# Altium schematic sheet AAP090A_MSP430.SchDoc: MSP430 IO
size 538 x 342 mm; Date: Not shown in title block; ApprovedBy: Not shown in title block; CheckedBy: Not shown in title block; Author: Not shown in title block; CompanyName: Not shown in title block; DrawnBy: LDN; Engineer: Not shown in title block; Organization: Not shown in title block; Address1: Not shown in title block; Address2: Not shown in title block; Address3: Not shown in title block; Address4: Not shown in title block; DocumentNumber: 2; Revision: Use project parameter SCH_Rev; SheetNumber: 2; SheetTotal: 6; PageSetup: Record=PageOptions¦CenterHorizontal=True¦CenterVertical=True¦PrintScale=1.00¦XCorrection=1.00¦YCorrection=1.00¦PrintKind=0¦BorderSize=5000000¦LeftOffset=0¦BottomOffset=0¦Orientation=2¦PaperLength=1000¦PaperWidth=1000¦Scale=100¦PaperSource=15¦PrintQuality=600¦MediaType=1¦DitherType=10¦PaperKind=Letter¦PrintScaleMode=1
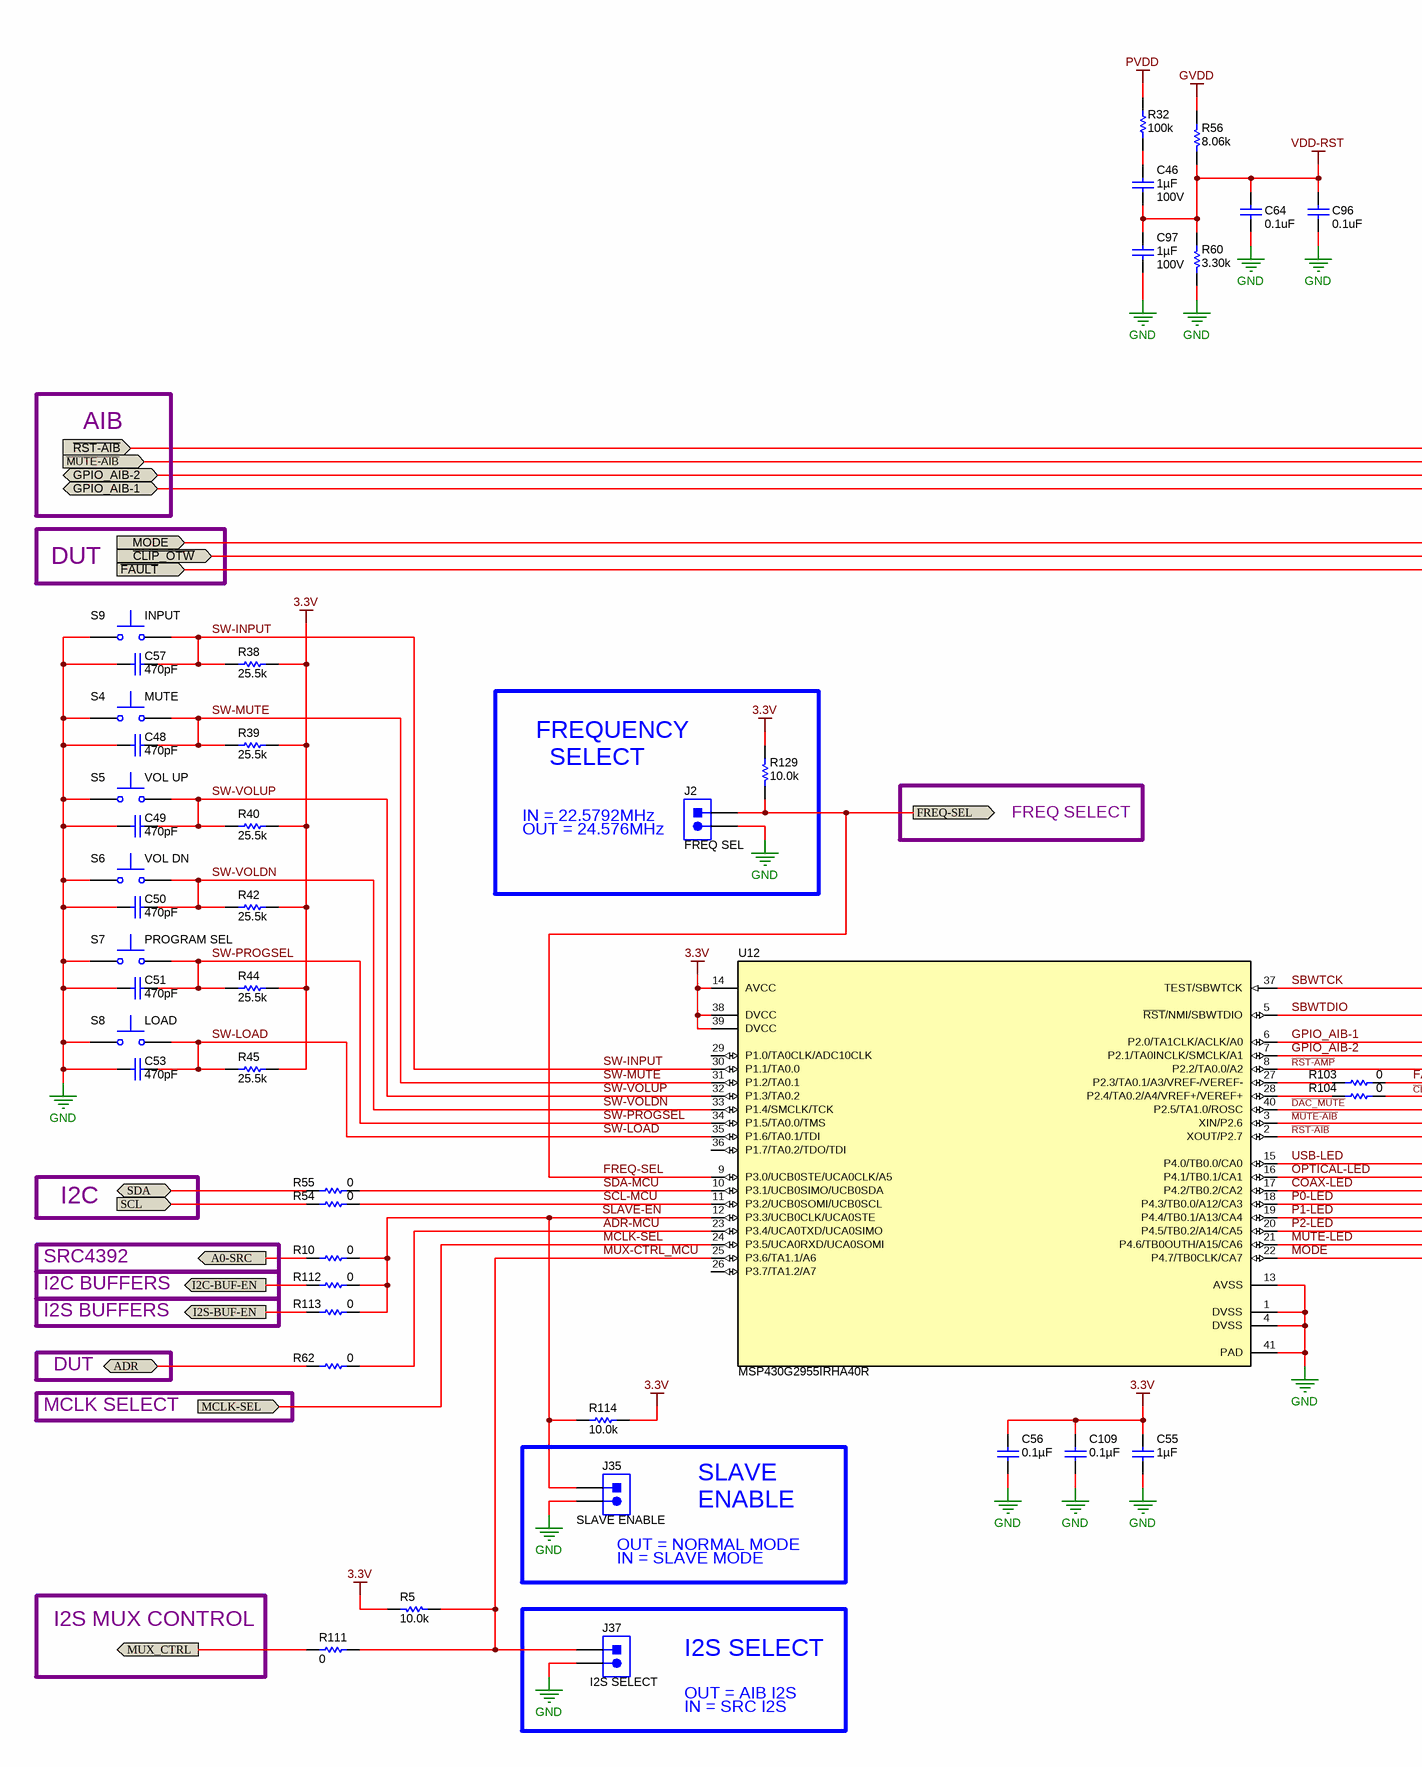
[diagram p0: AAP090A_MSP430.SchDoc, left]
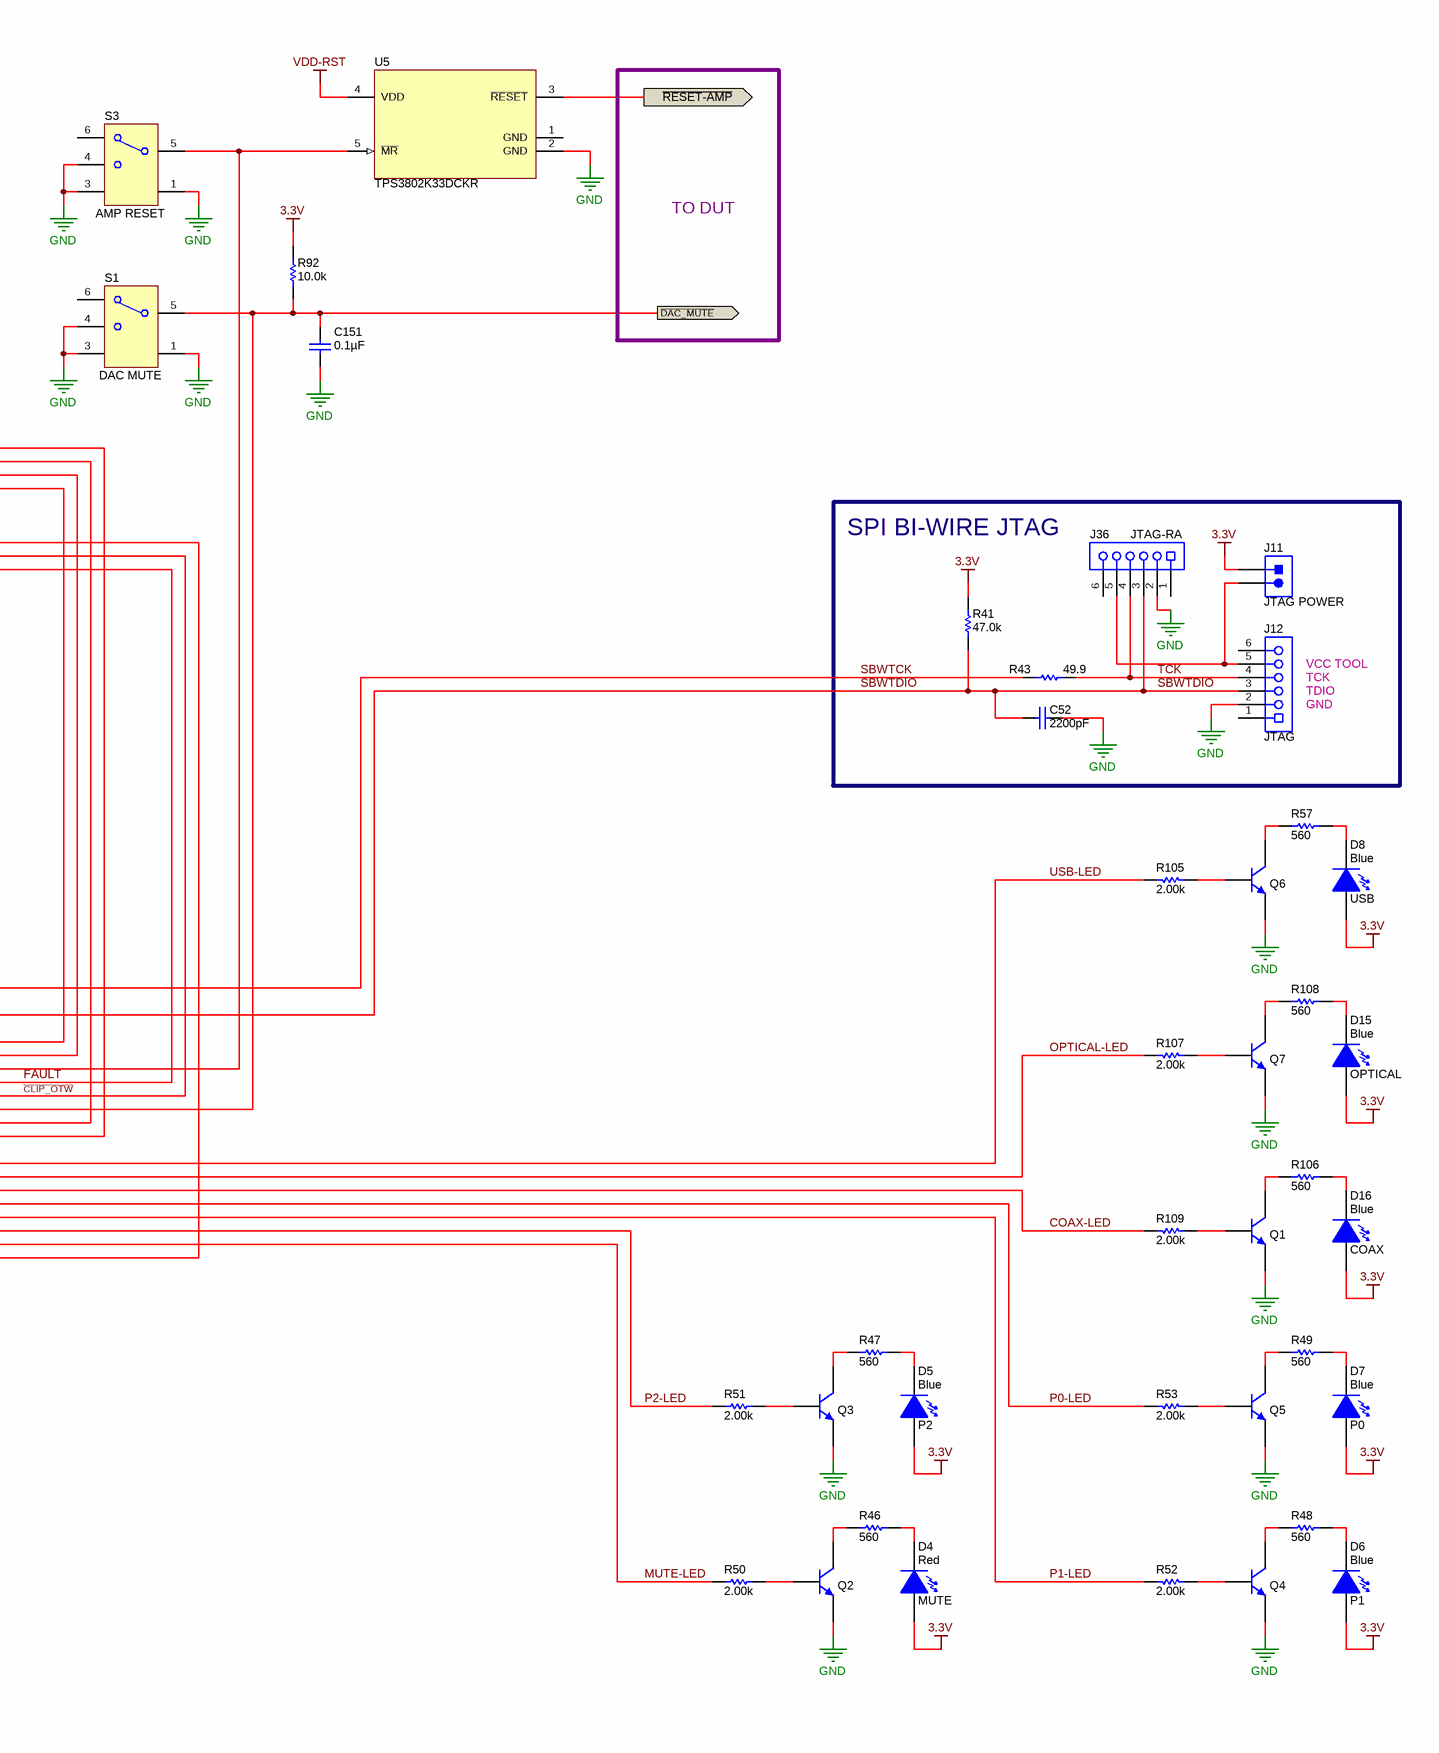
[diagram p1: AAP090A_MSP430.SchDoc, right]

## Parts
C46  ValueDisplayed: 1µF  Value2: 100V  [1206_180L]  (hidden comment: GRM31CR72A105KA01L)
C48  ValueDisplayed: 470pF  [0402L]  (hidden comment: GRM1555C1E471JA01D)
C49  ValueDisplayed: 470pF  [0402L]  (hidden comment: GRM1555C1E471JA01D)
C50  ValueDisplayed: 470pF  [0402L]  (hidden comment: GRM1555C1E471JA01D)
C51  ValueDisplayed: 470pF  [0402L]  (hidden comment: GRM1555C1E471JA01D)
C52  ValueDisplayed: 2200pF  [0603L]  (hidden comment: 885012206036)
C53  ValueDisplayed: 470pF  [0402L]  (hidden comment: GRM1555C1E471JA01D)
C55  ValueDisplayed: 1µF  [0402L]  (hidden comment: GRM152R60J105ME15D)
C56  ValueDisplayed: 0.1µF  [0402L]  (hidden comment: GRM155R71A104KA01D)
C57  ValueDisplayed: 470pF  [0402L]  (hidden comment: GRM1555C1E471JA01D)
C64  value 0.1uF  [0603L]  (hidden comment: C0603C104K5RACTU)
C96  value 0.1uF  [0603L]  (hidden comment: C0603C104K5RACTU)
C97  ValueDisplayed: 1µF  Value2: 100V  [1206_180L]  (hidden comment: GRM31CR72A105KA01L)
C109  ValueDisplayed: 0.1µF  [0402L]  (hidden comment: GRM155R71A104KA01D)
C151  ValueDisplayed: 0.1µF  [0402L]  (hidden comment: GRM155R71A104KA01D)
D4  MUTE  value Red  [LED_LTST-C190_Red]
D5  P2  value Blue  [LB Q39G_BLUE]
D6  P1  value Blue  [LB Q39G_BLUE]
D7  P0  value Blue  [LB Q39G_BLUE]
D8  USB  value Blue  [LB Q39G_BLUE]
D15  OPTICAL  value Blue  [LB Q39G_BLUE]
D16  COAX  value Blue  [LB Q39G_BLUE]
J2  FREQ SEL  [Sullins_PBC02SAAN]
J11  JTAG POWER  [Sullins_PBC02SAAN]
J12  JTAG  [Mill-Max_851-XX-006-10-001000]
J35  SLAVE ENABLE  [Sullins_PBC02SAAN]
J36  JTAG-RA  [SULLINS_LPPB061NGCN-RC]
J37  I2S SELECT  [Sullins_PBC02SAAN]
Q1  MMBT2222A  [SOT-23]  (value not drawn)
Q2  MMBT2222A  [SOT-23]  (value not drawn)
Q3  MMBT2222A  [SOT-23]  (value not drawn)
Q4  MMBT2222A  [SOT-23]  (value not drawn)
Q5  MMBT2222A  [SOT-23]  (value not drawn)
Q6  MMBT2222A  [SOT-23]  (value not drawn)
Q7  MMBT2222A  [SOT-23]  (value not drawn)
R5  ValueDisplayed: 10.0k  [0201L]  (hidden comment: RC0201FR-0710KL)
R10  ValueDisplayed: 0  [0603L]  (hidden comment: DNP)
R32  ValueDisplayed: 100k  [0603L]  (hidden comment: RC0603FR-07100KL)
R38  ValueDisplayed: 25.5k  [0201L]  (hidden comment: RC0201FR-0725K5L)
R39  ValueDisplayed: 25.5k  [0201L]  (hidden comment: RC0201FR-0725K5L)
R40  ValueDisplayed: 25.5k  [0201L]  (hidden comment: RC0201FR-0725K5L)
R41  ValueDisplayed: 47.0k  [0402L]  (hidden comment: RC0402FR-0747KL)
R42  ValueDisplayed: 25.5k  [0201L]  (hidden comment: RC0201FR-0725K5L)
R43  ValueDisplayed: 49.9  [0402L]  (hidden comment: RC0402FR-0749R9L)
R44  ValueDisplayed: 25.5k  [0201L]  (hidden comment: RC0201FR-0725K5L)
R45  ValueDisplayed: 25.5k  [0201L]  (hidden comment: RC0201FR-0725K5L)
R46  ValueDisplayed: 560  [0603L]  (hidden comment: RC0603JR-07560RL)
R47  ValueDisplayed: 560  [0603L]  (hidden comment: RC0603JR-07560RL)
R48  ValueDisplayed: 560  [0603L]  (hidden comment: RC0603JR-07560RL)
R49  ValueDisplayed: 560  [0603L]  (hidden comment: RC0603JR-07560RL)
R50  ValueDisplayed: 2.00k  [0603L]  (hidden comment: RC0603FR-072KL)
R51  ValueDisplayed: 2.00k  [0603L]  (hidden comment: RC0603FR-072KL)
R52  ValueDisplayed: 2.00k  [0603L]  (hidden comment: RC0603FR-072KL)
R53  ValueDisplayed: 2.00k  [0603L]  (hidden comment: RC0603FR-072KL)
R54  ValueDisplayed: 0  [0603L]  (hidden comment: ERJ-3GEY0R00V)
R55  ValueDisplayed: 0  [0603L]  (hidden comment: ERJ-3GEY0R00V)
R56  ValueDisplayed: 8.06k  [0603L]  (hidden comment: RC0603FR-078K06L)
R57  ValueDisplayed: 560  [0603L]  (hidden comment: RC0603JR-07560RL)
R60  ValueDisplayed: 3.30k  [0603L]  (hidden comment: RC0603FR-073K3L)
R62  ValueDisplayed: 0  [0603L]  (hidden comment: ERJ-3GEY0R00V)
R92  ValueDisplayed: 10.0k  [0402L]  (hidden comment: ERJ-2RKF1002X)
R103  ValueDisplayed: 0  [0603L]  (hidden comment: ERJ-3GEY0R00V)
R104  ValueDisplayed: 0  [0603L]  (hidden comment: ERJ-3GEY0R00V)
R105  ValueDisplayed: 2.00k  [0603L]  (hidden comment: RC0603FR-072KL)
R106  ValueDisplayed: 560  [0603L]  (hidden comment: RC0603JR-07560RL)
R107  ValueDisplayed: 2.00k  [0603L]  (hidden comment: RC0603FR-072KL)
R108  ValueDisplayed: 560  [0603L]  (hidden comment: RC0603JR-07560RL)
R109  ValueDisplayed: 2.00k  [0603L]  (hidden comment: RC0603FR-072KL)
R111  ValueDisplayed: 0  [0402L]  (hidden comment: ERJ-2GE0R00X)
R112  ValueDisplayed: 0  [0603L]  (hidden comment: ERJ-3GEY0R00V)
R113  ValueDisplayed: 0  [0603L]  (hidden comment: ERJ-3GEY0R00V)
R114  ValueDisplayed: 10.0k  [0201L]  (hidden comment: RC0201FR-0710KL)
R129  ValueDisplayed: 10.0k  [0201L]  (hidden comment: RC0201FR-0710KL)
S1  DAC MUTE  [SW_200USP1T1A1M2]
S3  AMP RESET  [SW_200USP1T1A1M2]
S4  MUTE  [SW_TL1015AF160QG]
S5  VOL UP  [SW_TL1015AF160QG]
S6  VOL DN  [SW_TL1015AF160QG]
S7  PROGRAM SEL  [SW_TL1015AF160QG]
S8  LOAD  [SW_TL1015AF160QG]
S9  INPUT  [SW_TL1015AF160QG]
U5  TPS3802K33DCKR  [DCK0005A_N]
U12  MSP430G2955IRHA40R  [RHA0040B]

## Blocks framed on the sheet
SPI BI-WIRE JTAG: C52 J11 J12 J36 R41 R43
I2S SELECT: J37

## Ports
A0-SRC (out), ADR (bidir), FREQ-SEL (out), GPIO_AIB-1 (bidir), GPIO_AIB-2 (bidir), I2C-BUF-EN (out), I2S-BUF-EN (out), MCLK-SEL (in), MODE (in), MUX_CTRL (out), SCL (in), SDA (bidir), ~{CLIP_OTW} (in), ~{DAC_MUTE} (out), ~{FAULT} (in), ~{MUTE-AIB} (in), ~{RESET-AMP} (out), ~{RST-AIB} (in)

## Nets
3.3V: C55.2 C56.2 C109.2 D4.1(A) D5.1(A) D6.1(A) D7.1(A) D8.1(A) D15.1(A) D16.1(A) J11.1 R5.2 R38.1 R39.1 R40.1 R41.2 R42.1 R44.1 R45.1 R92.1 R114.2 R129.2 U12.14(AVCC) U12.38(DVCC) U12.39(DVCC)
GND: C48.2 C49.2 C50.2 C51.2 C52.1 C53.2 C55.1 C56.1 C57.2 C64.2 C96.2 C97.1 C109.1 C151.1 J2.2 J12.2 J35.2 J36.2 J37.2 Q1.2(E) Q2.2(E) Q3.2(E) Q4.2(E) Q5.2(E) Q6.2(E) Q7.2(E) R60.1 S1.1 S1.3 S1.4 S3.1 S3.3 S3.4 S4.1 S5.1 S6.1 S7.1 S8.1 S9.1 U5.2(GND) U12.1(DVSS) U12.4(DVSS) U12.13(AVSS) U12.41(PAD)
GVDD: R56.2
PVDD: R32.2
VDD-RST: C46.1 C64.1 C96.1 C97.2 R56.1 R60.2 U5.4(VDD)
~{CLIP_OTW}: R104.2 ; port ~{CLIP_OTW}
~{DAC_MUTE}: C151.2 R92.2 S1.5(COM) U12.40(P2.5/TA1.0/ROSC) ; port ~{DAC_MUTE}
~{FAULT}: R103.2 ; port ~{FAULT}
~{MUTE-AIB}: U12.3(XIN/P2.6) ; port ~{MUTE-AIB}
~{RESET-AMP}: U5.3(~{RESET}) ; port ~{RESET-AMP}
~{RST-AIB}: U12.2(XOUT/P2.7) ; port ~{RST-AIB}
~{RST-AMP}: S3.5(COM) U5.5(~{MR}) U12.8(P2.2/TA0.0/A2)
A0-SRC: R10.1 ; port A0-SRC
ADR: R62.1 ; port ADR
ADR-MCU: R62.2 U12.23(P3.4/UCA0TXD/UCA0SIMO)
COAX-LED: R109.2 U12.17(P4.2/TB0.2/CA2)
FREQ-SEL: J2.1 R129.1 U12.9(P3.0/UCB0STE/UCA0CLK/A5) ; port FREQ-SEL
GPIO_AIB-1: U12.6(P2.0/TA1CLK/ACLK/A0) ; port GPIO_AIB-1
GPIO_AIB-2: U12.7(P2.1/TA0INCLK/SMCLK/A1) ; port GPIO_AIB-2
I2C-BUF-EN: R112.1 ; port I2C-BUF-EN
I2S-BUF-EN: R113.1 ; port I2S-BUF-EN
MCLK-SEL: U12.24(P3.5/UCA0RXD/UCA0SOMI) ; port MCLK-SEL
MODE: U12.22(P4.7/TB0CLK/CA7) ; port MODE
MUTE-LED: R50.2 U12.21(P4.6/TB0OUTH/A15/CA6)
MUX-CTRL_MCU: J37.1 R5.1 R111.1 U12.25(P3.6/TA1.1/A6)
MUX_CTRL: R111.2 ; port MUX_CTRL
OPTICAL-LED: R107.2 U12.16(P4.1/TB0.1/CA1)
P0-LED: R53.2 U12.18(P4.3/TB0.0/A12/CA3)
P1-LED: R52.2 U12.19(P4.4/TB0.1/A13/CA4)
P2-LED: R51.2 U12.20(P4.5/TB0.2/A14/CA5)
SBWTCK: R43.1 U12.37(TEST/SBWTCK)
SBWTDIO: C52.2 J12.3 J36.3 R41.1 U12.5(~{RST}/NMI/SBWTDIO)
SCL: R54.1 ; port SCL
SCL-MCU: R54.2 U12.11(P3.2/UCB0SOMI/UCB0SCL)
SDA: R55.1 ; port SDA
SDA-MCU: R55.2 U12.10(P3.1/UCB0SIMO/UCB0SDA)
SLAVE-EN: J35.1 R10.2 R112.2 R113.2 R114.1 U12.12(P3.3/UCB0CLK/UCA0STE)
SW-INPUT: C57.1 R38.2 S9.2 U12.30(P1.1/TA0.0)
SW-LOAD: C53.1 R45.2 S8.2 U12.35(P1.6/TA0.1/TDI)
SW-MUTE: C48.1 R39.2 S4.2 U12.31(P1.2/TA0.1)
SW-PROGSEL: C51.1 R44.2 S7.2 U12.34(P1.5/TA0.0/TMS)
SW-VOLDN: C50.1 R42.2 S6.2 U12.33(P1.4/SMCLK/TCK)
SW-VOLUP: C49.1 R40.2 S5.2 U12.32(P1.3/TA0.2)
TCK: J12.4 J36.4 R43.2
USB-LED: R105.2 U12.15(P4.0/TB0.0/CA0)
NetC46_2: C46.2 R32.1
NetD4_2: D4.2(K) R46.1
NetD5_2: D5.2(K) R47.1
NetD6_2: D6.2(K) R48.1
NetD7_2: D7.2(K) R49.1
NetD8_2: D8.2(K) R57.1
NetD15_2: D15.2(K) R108.1
NetD16_2: D16.2(K) R106.1
NetJ11_2: J11.2 J12.5 J36.5
NetQ1_1: Q1.1(B) R109.1
NetQ1_3: Q1.3(C) R106.2
NetQ2_1: Q2.1(B) R50.1
NetQ2_3: Q2.3(C) R46.2
NetQ3_1: Q3.1(B) R51.1
NetQ3_3: Q3.3(C) R47.2
NetQ4_1: Q4.1(B) R52.1
NetQ4_3: Q4.3(C) R48.2
NetQ5_1: Q5.1(B) R53.1
NetQ5_3: Q5.3(C) R49.2
NetQ6_1: Q6.1(B) R105.1
NetQ6_3: Q6.3(C) R57.2
NetQ7_1: Q7.1(B) R107.1
NetQ7_3: Q7.3(C) R108.2
NetR103_1: R103.1 U12.27(P2.3/TA0.1/A3/VREF-/VEREF-)
NetR104_1: R104.1 U12.28(P2.4/TA0.2/A4/VREF+/VEREF+)

Not connected (* = marked no-connect by the designer): J12 1 6; J36 1 6; S1 6; S3 6; U5 1(GND); U12 26(P3.7/TA1.2/A7) 29(P1.0/TA0CLK/ADC10CLK) 36(P1.7/TA0.2/TDO/TDI)

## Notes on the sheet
- TO DUT
- AIB
- DUT
- (near J12) VCC TOOL
- (near J12) TDIO
- (near J12) TCK
- (near J12) GND
- FREQUENCY
- SELECT
- OUT = 24.576MHz
- IN = 22.5792MHz
- FREQ SELECT
- I2C
- I2C BUFFERS
- SRC4392
- I2S BUFFERS
- MCLK SELECT
- SLAVE
- ENABLE
- (near J35) OUT = NORMAL MODE
- (near J35) IN = SLAVE MODE
- I2S MUX CONTROL
- OUT = AIB I2S
- IN = SRC I2S

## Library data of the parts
C46 C97 = GRM31CR72A105KA01L: CAP, CERM, 1 µF, 100 V, +/- 10%, X7R, 1206; Manufacturer: MuRata; Polarized: N; CompType: Capacitor; Value: 1uF; U/M: EA; Cap_F: 0.000001; Tolerance_%: 10; Value1: Unknown; VDC_V: 100; TaMin_C: -55; TaMax_C: 125; Cap_Case: 2220; SizeArea_mm2: 5.12; SizeAreaWB_mm2: 10.92; SizeX_mm: 3.2; SizeY_mm: 1.6; SizeZ_mm: 1.8; AEC Category: Q200
C48-C51 C53 C57 = GRM1555C1E471JA01D: CAP, CERM, 470 pF, 25 V, +/- 5%, C0G/NP0, 0402; Manufacturer: MuRata; Polarized: N; CompType: Capacitor; Value: 470pF; U/M: EA; Cap_F: 0.00000000047; Tolerance_%: 5; Value1: Unknown; VDC_V: 25; Value2: 25V; TaMin_C: -55; TaMax_C: 125; Cap_Case: 0402; AEC Category: Q200; SizeArea_mm2: 0.5; SizeAreaWB_mm2: 3; SizeX_mm: 1; SizeZ_mm: 0.6
C52 = 885012206036: CAP, CERM, 2200 pF, 16 V, +/- 10%, X7R, 0603; Manufacturer: Wurth Elektronik; Polarized: N; CompType: Capacitor; Value: 2200pF; U/M: EA; Cap_F: 0.0000000022; Tolerance_%: 10; Value1: Unknown; VDC_V: 16; Value2: 16V; TaMin_C: -55; TaMax_C: 125; Cap_Case: 0603; AEC Category: Q200; SizeArea_mm2: 1.28; SizeAreaWB_mm2: 4.68; SizeX_mm: 1.6; SizeY_mm: 0.8; SizeZ_mm: 1
C55 = GRM152R60J105ME15D: CAP, CERM, 1 µF, 6.3 V,+/- 20%, X5R, 0402; Manufacturer: MuRata; Polarized: N; CompType: Capacitor; Value: 1uF; U/M: EA; Cap_F: 0.000001; Tolerance_%: 20; VDC_V: 6.3; Value2: 6.3V; TaMin_C: -55; TaMax_C: 85; Cap_Case: 0402; SizeArea_mm2: 0.5; SizeAreaWB_mm2: 3; SizeX_mm: 1; SizeZ_mm: 0.6; AEC Category: Q200; Green_Lifecycle: Active; Green_REACh: Passed
C56 C109 C151 = GRM155R71A104KA01D: CAP, CERM, 0.1 µF, 10 V, +/- 10%, X7R, 0402; Manufacturer: MuRata; Polarized: N; CompType: Capacitor; Value: 0.1uF; U/M: EA; Cap_F: 0.0000001; Tolerance_%: 10; Value1: Unknown; Value2: 10V; TaMin_C: -55; TaMax_C: 125; Cap_Case: 0402; AEC Category: Q200
C64 C96 = C0603C104K5RACTU: CAP, CERM, 0.1 µF, 50 V, +/- 10%, X7R, 0603; Manufacturer: Kemet; Polarized: N; CompType: Capacitor; ValueDisplayed: 0.1µF; U/M: EA; Cap_F: 0.0000001; Tolerance_%: 10; Value1: Unknown; VDC_V: 50; Value2: 50V; TaMin_C: -55; TaMax_C: 125; Cap_Case: 0603; AEC Category: Q200
D4 = LTST-C190CKT: LED, Red, SMD; Manufacturer: Lite-On; Vf_V: 2; Value2: 2V; Io_A: 0.02; Tjmax_C: 85; Power_TotalModule: 0.0625; Value1: 0.0625W; U/M: EA
D5-D8 D15 D16 = LB Q39G-L2N2-35-1: LED, Blue, SMD; Manufacturer: OSRAM; Vf_V: 2.85; Value2: 2.85V; Io_A: 0.15; Tjmax_C: 95; Value1: W; U/M: EA
J2 J11 J35 J37 = PBC02SAAN: Header, 100mil, 2x1, Gold, TH; Manufacturer: Sullins Connector Solutions; SymbolCreator: a0412235; Pitch_mm: 2.54; Gender: Male; Shrouded: N; Row_Count: 1; Current_A: 3; Voltage_V: 1800; Cert_UL: Y
J12 = 851-43-006-10-001000: Receptacle, 50mil, 6x1, Gold, TH; Manufacturer: Mill-Max; SymbolCreator: a0411947; CompType: Socket Strip; Green_Lifecycle: Active; Green_REACh: Passed
J36 = LPPB061NGCN-RC: Receptacle, 50mil, 6x1, Gold, R/A, TH; Manufacturer: Sullins Connector Solutions; SymbolCreator: a0411947
Q1-Q7 = MMBT2222A, Fairchild Semiconductor: Transistor, NPN, 40 V, 0.15 A, SOT-23; CompType: BJT; PNP: 0; NPN: 1; Vceo_V: 40; Vcesat1_V: 0.3; Value: 40 V; IcRated_A: 0.15; Value1: 0.15 A; HfeMax: 300; TaMin_C: -55; TaMax_C: 150; U/M: EA; AEC Category: Q101
R5 R114 R129 = RC0201FR-0710KL: RES, 10.0 k, 1%, 0.05 W, 0201; Manufacturer: Yageo America; CompType: Resistor; Value: 10.0k; Res_ohm: 10000; Value_Code: 10k0; Tolerance_%: 1; Power_W: 0.05; Value2: 0.05W; VDC_V: 25; TempCo: 200 ppm/C; EIA_Code: E96; U/M: EA; SizeArea_mm2: 0.18; SizeX_mm: 0.6; SizeY_mm: 0.3; SizeZ_mm: 0.26; AEC Category: Q200; AEC Qualified: N
R10 R54 R55 R62 R103 R104 R112 R113 = ERJ-3GEY0R00V: RES, 0, 5%, 0.1 W, 0603; Manufacturer: Panasonic; CompType: Resistor; Value: 0; Value_Code: 0000; Tolerance_%: 5; Power_W: 0.1; Value2: 0.1W; VDC_V: 50; TempCo: 600 ppm/C; EIA_Code: E24; U/M: EA; AEC Category: Q200; SizeArea_mm2: 1.28; SizeX_mm: 1.6; SizeY_mm: 0.8; SizeZ_mm: 1; Green_Lifecycle: Active; Green_REACh: Passed
R32 = RC0603FR-07100KL: RES, 100 k, 1%, 0.1 W, 0603; Manufacturer: Yageo America; CompType: Resistor; Value: 100k; Res_ohm: 100000; Tolerance_%: 1; Power_W: 0.1; Value2: 0.1W; VDC_V: 150; TempCo: 200 ppm/C; EIA_Code: E96; U/M: EA; AEC Category: Q200; SizeArea_mm2: 1.28; SizeX_mm: 1.6; SizeY_mm: 0.8; Green_Lifecycle: Active; Green_REACh: Passed
R38-R40 R42 R44 R45 = RC0201FR-0725K5L: RES, 25.5 k, 1%, 0.05 W, 0201; Manufacturer: Yageo America; CompType: Resistor; Value: 25.5k; Res_ohm: 25500; Value_Code: 25k5; Tolerance_%: 1; Power_W: 0.05; Value2: 0.05W; VDC_V: 25; TempCo: 200 ppm/C; SizeArea_mm2: 0.18; SizeX_mm: 0.6; SizeY_mm: 0.3; SizeZ_mm: 0.26; EIA_Code: E96; U/M: EA; AEC Category: Q200; AEC Qualified: N
R41 = RC0402FR-0747KL: RES, 47.0 k, 1%, 0.0625 W, 0402; Manufacturer: Yageo America; CompType: Resistor; Value: 47.0k; Res_ohm: 47000; Value_Code: 47k0; Tolerance_%: 1; Power_W: 0.0625; VDC_V: 50; TempCo: 100 ppm/C; SizeArea_mm2: 0.5; SizeZ_mm: 0.6; U/M: EA; AEC Category: Q200; AEC Qualified: N; Green_Lifecycle: Active; Green_REACh: Passed
R43 = RC0402FR-0749R9L: RES, 49.9, 1%, 0.063 W, 0402; Manufacturer: Yageo America; CompType: Resistor; Value: 49.9; Value_Code: 49R9; Tolerance_%: 1; Power_W: 0.063; Value2: 0.063W; VDC_V: 50; TempCo: 100 ppm/C; SizeArea_mm2: 0.5; SizeZ_mm: 0.6; EIA_Code: E96; U/M: EA; AEC Category: Q200; AEC Qualified: N; Green_Lifecycle: Active; Green_REACh: Passed
R46-R49 R57 R106 R108 = RC0603JR-07560RL: RES, 560, 5%, 0.1 W, 0603; Manufacturer: Yageo America; CompType: Resistor; Value: 560; Value_Code: 560R; Tolerance_%: 5; Power_W: 0.1; Value2: 0.1W; VDC_V: 50; TempCo: 100 ppm/C; EIA_Code: E24; U/M: EA; AEC Category: Q200; SizeArea_mm2: 1.28; SizeX_mm: 1.6; SizeY_mm: 0.8; SizeZ_mm: 1
R50-R53 R105 R107 R109 = RC0603FR-072KL: RES, 2.00 k, 1%, 0.1 W, 0603; Manufacturer: Yageo America; CompType: Resistor; Value: 2.00k; Res_ohm: 2000; Value_Code: 2k00; Tolerance_%: 1; Power_W: 0.1; Value2: 0.1W; VDC_V: 150; TempCo: 200 ppm/C; EIA_Code: E96; U/M: EA; AEC Category: Q200; SizeArea_mm2: 1.28; SizeX_mm: 1.6; SizeY_mm: 0.8; Green_Lifecycle: Active; Green_REACh: Passed
R56 = RC0603FR-078K06L: RES, 8.06 k, 1%, 0.1 W, 0603; Manufacturer: Yageo America; CompType: Resistor; Value: 8.06k; Res_ohm: 8060; Value_Code: 8k06; Tolerance_%: 1; Power_W: 0.1; Value2: 0.1W; VDC_V: 150; TempCo: 200 ppm/C; EIA_Code: E96; U/M: EA; AEC Category: Q200; SizeArea_mm2: 1.28; SizeX_mm: 1.6; SizeY_mm: 0.8; Green_Lifecycle: Active; Green_REACh: Passed
R60 = RC0603FR-073K3L: RES, 3.30 k, 1%, 0.1 W, 0603; Manufacturer: Yageo America; CompType: Resistor; Value: 3.30k; Res_ohm: 3300; Value_Code: 3k30; Tolerance_%: 1; Power_W: 0.1; Value2: 0.1W; VDC_V: 150; TempCo: 200 ppm/C; U/M: EA; AEC Category: Q200
R92 = ERJ-2RKF1002X: RES, 10.0 k, 1%, 0.1 W, 0402; Manufacturer: Panasonic; CompType: Resistor; Value: 10.0k; Res_ohm: 10000; Value_Code: 10k0; Tolerance_%: 1; Power_W: 0.1; Value2: 0.1W; VDC_V: 50; TempCo: 100 ppm/C; EIA_Code: E96; U/M: EA; AEC Category: Q200; SizeArea_mm2: 0.5; SizeZ_mm: 0.6; Green_Lifecycle: Active; Green_REACh: Passed
R111 = ERJ-2GE0R00X: RES, 0, 5%, 0.063 W, 0402; Manufacturer: Panasonic; CompType: Resistor; Value: 0; Value_Code: 0000; Tolerance_%: 5; Power_W: 0.063; Value2: 0.063W; VDC_V: 50; TempCo: 600 ppm/C; EIA_Code: E24; U/M: EA; AEC Category: Q200; SizeArea_mm2: 0.5; SizeX_mm: 1; SizeZ_mm: 0.6
S1 S3 = 200USP1T1A1M2RE: Switch, SPDT, On-On, 2 Pos, TH; Manufacturer: E-Switch; SymbolCreator: Altium; VDC_V: 20; PositionCount: 2; CurrentRating_mA: 400
S4-S9 = TL1015AF160QG: Switch, Tactile, SPST-NO, 0.05A, 12V, SMT; Manufacturer: E-Switch; SymbolCreator: a0412235; VDC_V: 12; SwitchFunction: Off-Mom; PositionCount: 1; CurrentRating_mA: 50
U5 = TPS3802K33DCKR: ULTRA-SMALL SUPPLY VOLTAGE SUPERVISORS, DCK0005A; Manufacturer: Texas Instruments; SymbolCreator: Altium; CompType: IC; U/M: EA
U12 = MSP430G2955IRHA40R: MIXED SIGNAL MICROCONTROLLER, RHA0040B (VQFN-40); Alternate PartNumber: MSP430G2955IRHA40T; Manufacturer: Texas Instruments; SymbolCreator: Altium; SizeArea_mm2: 37.8225; SizeAreaWB_mm2: 66.4225; SizeX_mm: 6.15; SizeZ_mm: 1; CompType: IC; U/M: EA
